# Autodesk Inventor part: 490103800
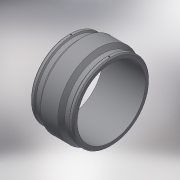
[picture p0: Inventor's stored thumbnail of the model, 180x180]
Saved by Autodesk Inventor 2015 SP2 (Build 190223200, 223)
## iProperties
Created: 2017-06
Part Number: 490103800
Material: Generic
Description: PLASSON COUPLER 800
Document SubType Name: Modeling
Designer: KIM
Mass: 79373.8 g
Surface Area: 30498.9 cm^2
Volume: 79373.8 cm^3
Density: 1 g/cm^3
Appearance: Default
Author: KIM
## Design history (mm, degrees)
derived "490103.ipt"
feature "Solid1::490103.ipt"
tag "TaggingFeature1"
body "Solid1"
other parameters: "d23" = 955, "d24" = 873, "d25" = 135 deg, "d27" = 135 deg, "d35" = 15, "d39" = 0, "d40" = 4, "d41" = 14, "d42" = 0, "d43" = 135 deg, "d44" = 55, "d46" = 6, "d47" = 0, "D_" = 955, "d_2" = 12
